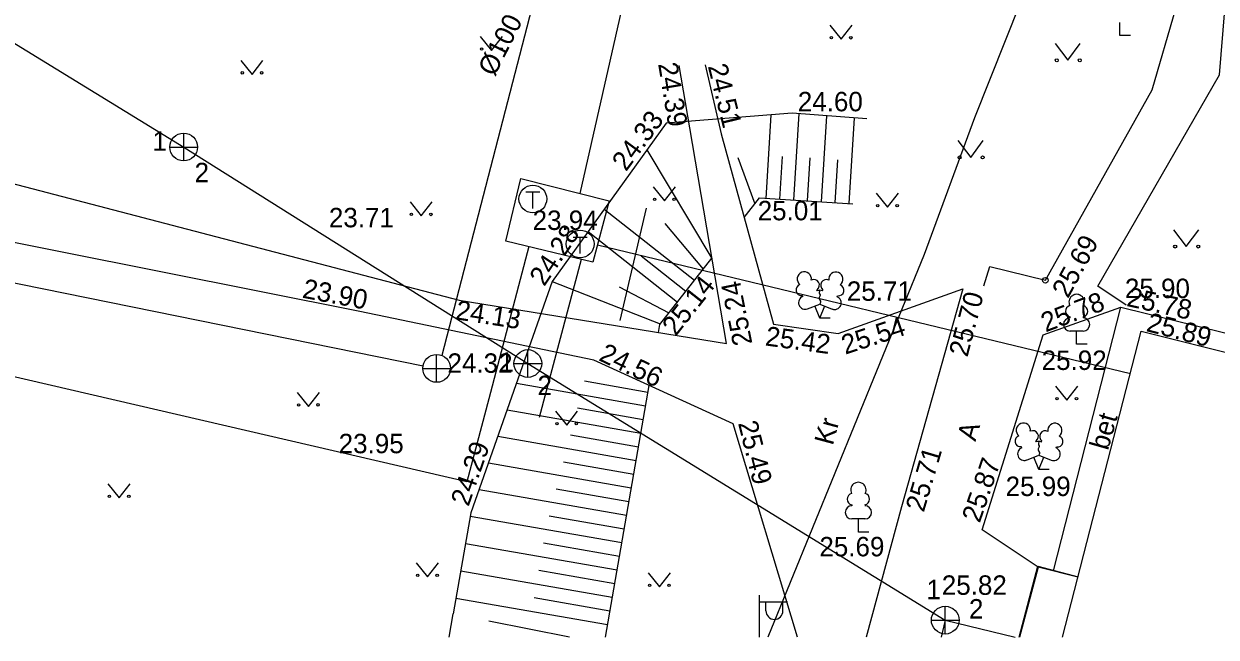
# Model space of a CAD drawing. Extents: x 714391 to 714584, y 6589993 to 6590151.
# Drawn here: x 714490.89 to 714533.84, y 6589992.71 to 6590014.81 of the extents above; entities that cross this region are included whole.
import ezdxf

# ---------------------------------------------------------------- set-up
doc = ezdxf.new("R2010")
doc.units = 0
for name, color, linetype in [('HALJASTUS', 7, 'Continuous'), ('HOONE', 7, 'Continuous'), ('HOONEDET', 7, 'Continuous'), ('KKAEV', 7, 'Continuous'), ('KORGUS', 7, 'Continuous'), ('KTRASS', 7, 'Continuous'), ('MPKAABEL', 7, 'Continuous'), ('POST', 7, 'Continuous'), ('PUU', 7, 'Continuous'), ('RAJATIS', 7, 'Continuous'), ('RELJEEF', 7, 'Continuous'), ('SKTRASS', 7, 'Continuous'), ('TEE', 7, 'Continuous'), ('TKAEV', 7, 'Continuous'), ('TORU NR', 7, 'Continuous'), ('TTRASS', 7, 'Continuous')]:
    doc.layers.add(name, color=color, linetype=linetype)

msp = doc.modelspace()

# ---------------------------------------------------------------- linework, layer by layer
at = {"layer": 'HALJASTUS'}
for p, q in [((714519.929, 6590014.762), (714520.334, 6590014.257)), ((714520.334, 6590014.257), (714520.729, 6590014.762)), ((714507.332, 6590014.356), (714507.737, 6590013.851)), ((714507.737, 6590013.851), (714508.132, 6590014.356)), ((714528.037, 6590014.107), (714528.5, 6590013.5)), ((714528.5, 6590013.5), (714528.946, 6590014.107)), ((714498.707, 6590013.498), (714499.112, 6590012.993)), ((714499.112, 6590012.993), (714499.507, 6590013.498)), ((714524.537, 6590010.607), (714525, 6590010)), ((714525, 6590010), (714525.446, 6590010.607)), ((714513.563, 6590008.937), (714513.968, 6590008.432)), ((714513.968, 6590008.432), (714514.363, 6590008.937)), ((714521.6, 6590008.711), (714522.005, 6590008.206)), ((714522.005, 6590008.206), (714522.4, 6590008.711)), ((714504.803, 6590008.395), (714505.208, 6590007.89)), ((714505.208, 6590007.89), (714505.603, 6590008.395)), ((714532.303, 6590007.395), (714532.766, 6590006.788)), ((714532.766, 6590006.788), (714533.212, 6590007.395)), ((714528.057, 6590001.758), (714528.462, 6590001.253)), ((714528.462, 6590001.253), (714528.857, 6590001.758)), ((714500.739, 6590001.532), (714501.144, 6590001.027)), ((714501.144, 6590001.027), (714501.539, 6590001.532)), ((714510.041, 6590000.855), (714510.446, 6590000.35)), ((714510.446, 6590000.35), (714510.841, 6590000.855)), ((714493.921, 6589998.236), (714494.326, 6589997.731)), ((714494.326, 6589997.731), (714494.721, 6589998.236)), ((714505.029, 6589995.391), (714505.434, 6589994.886)), ((714505.434, 6589994.886), (714505.829, 6589995.391)), ((714513.382, 6589995.03), (714513.787, 6589994.525)), ((714513.787, 6589994.525), (714514.182, 6589995.03))]:
    msp.add_line(p, q, dxfattribs=at)
for centre, radius in [((714519.981, 6590014.312), 0.0428), ((714520.681, 6590014.312), 0.0452), ((714507.384, 6590013.906), 0.0428), ((714508.084, 6590013.906), 0.0452), ((714528.099, 6590013.5), 0.055), ((714528.928, 6590013.5), 0.055), ((714498.759, 6590013.048), 0.0428), ((714499.459, 6590013.048), 0.0452), ((714524.599, 6590010), 0.055), ((714525.428, 6590010), 0.055), ((714513.615, 6590008.488), 0.0428), ((714514.315, 6590008.488), 0.0452), ((714521.652, 6590008.262), 0.0428), ((714522.352, 6590008.262), 0.0452), ((714504.855, 6590007.946), 0.0428), ((714505.555, 6590007.946), 0.0452), ((714532.365, 6590006.788), 0.055), ((714533.194, 6590006.788), 0.055), ((714500.791, 6590001.082), 0.0428), ((714501.491, 6590001.082), 0.0452), ((714528.109, 6590001.308), 0.0428), ((714528.809, 6590001.308), 0.0452), ((714510.093, 6590000.405), 0.0428), ((714510.793, 6590000.405), 0.0452), ((714493.973, 6589997.786), 0.0428), ((714494.673, 6589997.786), 0.0452), ((714505.081, 6589994.942), 0.0428), ((714505.781, 6589994.942), 0.0452), ((714513.434, 6589994.58), 0.0428), ((714514.134, 6589994.58), 0.0452)]:
    msp.add_circle(centre, radius, dxfattribs=at)
at = {"layer": 'HOONE'}
for points in [[(714528.305, 6589992.711), (714531.142, 6590003.734), (714541.598, 6590001.124)], [(714526.74, 6589992.711), (714527.42, 6589995.271), (714528.876, 6589994.89)], [(714527.427, 6589995.234), (714526.753, 6589992.711)]]:
    msp.add_lwpolyline(points, dxfattribs=at)
at = {"layer": 'HOONEDET'}
msp.add_lwpolyline([(714527.976, 6589995.097), (714530.413, 6590004.606), (714540.577, 6590002.096), (714542.446, 6590001.618), (714540.308, 6589992.711)], dxfattribs=at)
at = {"layer": 'KKAEV'}
for p, q in [((714496.65, 6590009.873), (714496.65, 6590010.873)), ((714496.15, 6590010.373), (714497.15, 6590010.373)), ((714505.763, 6590001.896), (714505.763, 6590002.896)), ((714509.047, 6590002.073), (714509.047, 6590003.073)), ((714508.547, 6590002.573), (714509.547, 6590002.573)), ((714505.263, 6590002.396), (714506.263, 6590002.396)), ((714524.082, 6589992.824), (714524.082, 6589993.824)), ((714523.582, 6589993.324), (714524.582, 6589993.324))]:
    msp.add_line(p, q, dxfattribs=at)
for centre in [(714496.65, 6590010.373), (714505.763, 6590002.396), (714509.047, 6590002.573), (714524.082, 6589993.324)]:
    msp.add_circle(centre, 0.5, dxfattribs=at)
at = {"layer": 'KORGUS'}
msp.add_circle((714527.69, 6590005.573), 0.1, dxfattribs=at)
at = {"layer": 'KTRASS'}
for p, q in [((714474.411, 6590024.03), (714496.65, 6590010.373)), ((714496.65, 6590010.373), (714509.047, 6590002.573)), ((714509.047, 6590002.573), (714524.082, 6589993.324)), ((714524.082, 6589993.324), (714523.935, 6589992.711)), ((714524.082, 6589993.324), (714526.599, 6589992.711))]:
    msp.add_line(p, q, dxfattribs=at)
at = {"layer": 'MPKAABEL'}
msp.add_lwpolyline([(714531.176, 6590026.61), (714525.138, 6590011.422), (714523.319, 6590006.504), (714517.694, 6589992.711)], dxfattribs=at)
at = {"layer": 'POST'}
for p, q in [((714517.395, 6589992.711), (714517.395, 6589994.229)), ((714517.395, 6589993.979), (714518.395, 6589993.979)), ((714517.622, 6589993.658), (714517.622, 6589993.979)), ((714518.234, 6589993.658), (714518.234, 6589993.979))]:
    msp.add_line(p, q, dxfattribs=at)
msp.add_arc((714517.928, 6589993.658), 0.306, 180, 0, dxfattribs=at)
at = {"layer": 'PUU'}
for p, q in [((714530.377, 6590014.391), (714530.377, 6590014.866)), ((714530.757, 6590014.391), (714530.377, 6590014.391)), ((714518.947, 6590004.987), (714518.932, 6590005.027)), ((714519.477, 6590005.197), (714519.462, 6590005.232)), ((714519.662, 6590005.192), (714519.677, 6590005.232)), ((714520.187, 6590004.977), (714520.202, 6590005.017)), ((714519.122, 6590004.542), (714519.567, 6590004.717)), ((714519.562, 6590004.207), (714519.387, 6590004.647)), ((714519.562, 6590004.207), (714519.742, 6590004.647)), ((714519.567, 6590004.717), (714520.007, 6590004.537)), ((714519.942, 6590004.207), (714519.562, 6590004.207)), ((714528.576, 6590004.249), (714528.576, 6590004.219)), ((714529.056, 6590004.249), (714529.056, 6590004.219)), ((714529.056, 6590003.744), (714528.576, 6590003.744)), ((714528.816, 6590003.269), (714528.816, 6590003.744)), ((714529.196, 6590003.269), (714528.816, 6590003.269)), ((714526.836, 6589999.539), (714526.821, 6589999.579)), ((714527.366, 6589999.749), (714527.351, 6589999.784)), ((714527.551, 6589999.744), (714527.566, 6589999.784)), ((714528.076, 6589999.529), (714528.091, 6589999.569)), ((714527.011, 6589999.094), (714527.456, 6589999.269)), ((714527.451, 6589998.759), (714527.276, 6589999.199)), ((714527.451, 6589998.759), (714527.631, 6589999.199)), ((714527.456, 6589999.269), (714527.896, 6589999.089)), ((714527.831, 6589998.759), (714527.451, 6589998.759)), ((714520.714, 6589997.476), (714520.714, 6589997.446)), ((714521.194, 6589997.476), (714521.194, 6589997.446)), ((714521.194, 6589996.971), (714520.714, 6589996.971)), ((714520.954, 6589996.496), (714520.954, 6589996.971)), ((714521.334, 6589996.496), (714520.954, 6589996.496))]:
    msp.add_line(p, q, dxfattribs=at)
for points in [[(714519.567, 6590005.212), (714519.547, 6590005.137), (714519.547, 6590005.117), (714519.557, 6590005.087), (714519.577, 6590005.052), (714519.582, 6590005.032), (714519.567, 6590004.997), (714519.542, 6590004.947), (714519.537, 6590004.922), (714519.542, 6590004.907), (714519.552, 6590004.877), (714519.587, 6590004.817), (714519.592, 6590004.797), (714519.587, 6590004.777), (714519.572, 6590004.742), (714519.567, 6590004.717)], [(714527.456, 6589999.764), (714527.436, 6589999.689), (714527.436, 6589999.669), (714527.446, 6589999.639), (714527.466, 6589999.604), (714527.471, 6589999.584), (714527.456, 6589999.549), (714527.431, 6589999.499), (714527.426, 6589999.474), (714527.431, 6589999.459), (714527.441, 6589999.429), (714527.476, 6589999.369), (714527.481, 6589999.349), (714527.476, 6589999.329), (714527.461, 6589999.294), (714527.456, 6589999.269)]]:
    msp.add_lwpolyline(points, dxfattribs=at)
for centre, radius, start, end in [((714519.005, 6590005.621), 0.256, 111.5027, 232.5173), ((714519.005, 6590005.621), 0.256, 350.4856, 111.5002), ((714520.141, 6590005.612), 0.256, 67.6168, 188.6314), ((714520.141, 6590005.612), 0.256, 306.5997, 67.6143), ((714518.906, 6590005.225), 0.202, 106.2979, 277.8684), ((714519.348, 6590005.399), 0.202, 305.1345, 116.705), ((714519.795, 6590005.395), 0.202, 62.412, 233.9825), ((714519.566, 6590004.974), 0.237, 66.7655, 111.5015), ((714520.234, 6590005.215), 0.202, 261.2486, 72.8191), ((714528.816, 6590004.789), 0.277, 332.5799, 207.4201), ((714528.816, 6590004.789), 0.277, 58.4864, 121.5136), ((714519.036, 6590004.765), 0.237, 111.5014, 291.5004), ((714520.097, 6590004.757), 0.237, 247.6166, 67.6155), ((714528.626, 6590004.457), 0.212, 105.2441, 257.079), ((714529.006, 6590004.457), 0.212, 282.921, 74.7559), ((714528.578, 6590003.981), 0.237, 90, 270), ((714529.053, 6590003.981), 0.237, 270, 90), ((714526.894, 6590000.173), 0.256, 111.5027, 232.5173), ((714526.894, 6590000.173), 0.256, 350.4856, 111.5002), ((714528.03, 6590000.164), 0.256, 67.6168, 188.6314), ((714528.03, 6590000.164), 0.256, 306.5997, 67.6143), ((714526.795, 6589999.777), 0.202, 106.2979, 277.8684), ((714527.237, 6589999.951), 0.202, 305.1345, 116.705), ((714527.684, 6589999.947), 0.202, 62.412, 233.9825), ((714528.123, 6589999.767), 0.202, 261.2486, 72.8191), ((714526.925, 6589999.317), 0.237, 111.5014, 291.5004), ((714527.455, 6589999.526), 0.237, 66.7655, 111.5015), ((714527.986, 6589999.309), 0.237, 247.6166, 67.6155), ((714520.954, 6589998.016), 0.277, 332.5799, 207.4201), ((714520.764, 6589997.684), 0.212, 105.2441, 257.079), ((714521.144, 6589997.684), 0.212, 282.921, 74.7559), ((714520.716, 6589997.209), 0.237, 90, 270), ((714521.191, 6589997.209), 0.237, 270, 90)]:
    msp.add_arc(centre, radius, start, end, dxfattribs=at)
at = {"layer": 'RAJATIS'}
msp.add_line((714513.314, 6590008.168), (714512.359, 6590004.124), dxfattribs=at)
at = {"layer": 'RELJEEF'}
for p, q in [((714517.802, 6590011.536), (714517.614, 6590008.525)), ((714518.807, 6590011.578), (714518.612, 6590008.463)), ((714519.804, 6590011.504), (714519.61, 6590008.4)), ((714520.802, 6590011.429), (714520.608, 6590008.338)), ((714513.336, 6590010.274), (714515.672, 6590006.359)), ((714516.609, 6590009.998), (714517.22, 6590008.322)), ((714518.21, 6590010.035), (714518.113, 6590008.494)), ((714519.209, 6590009.986), (714519.111, 6590008.431)), ((714520.206, 6590009.918), (714520.109, 6590008.369)), ((714511.8, 6590008.139), (714515.052, 6590005.574)), ((714513.976, 6590007.615), (714515.362, 6590005.967)), ((714511.215, 6590007.327), (714514.433, 6590004.789)), ((714513.125, 6590006.457), (714514.743, 6590005.182)), ((714509.921, 6590005.528), (714513.814, 6590004.004)), ((714512.335, 6590005.341), (714514.123, 6590004.396)), ((714508.633, 6590001.862), (714513.289, 6590001.053)), ((714511.088, 6590001.943), (714513.374, 6590001.546)), ((714508.297, 6590000.906), (714513.117, 6590000.068)), ((714510.834, 6590000.972), (714513.203, 6590000.561)), ((714507.961, 6589999.949), (714512.946, 6589999.083)), ((714510.58, 6590000.001), (714513.032, 6589999.575)), ((714507.625, 6589998.993), (714512.775, 6589998.098)), ((714510.327, 6589999.03), (714512.861, 6589998.59)), ((714507.289, 6589998.036), (714512.604, 6589997.112)), ((714510.073, 6589998.06), (714512.689, 6589997.605)), ((714506.972, 6589997.076), (714512.433, 6589996.127)), ((714509.819, 6589997.089), (714512.518, 6589996.62)), ((714506.8, 6589996.091), (714512.261, 6589995.142)), ((714509.617, 6589996.109), (714512.347, 6589995.634)), ((714509.445, 6589995.124), (714512.176, 6589994.649)), ((714506.628, 6589995.106), (714512.09, 6589994.157)), ((714506.457, 6589994.121), (714511.919, 6589993.171)), ((714509.273, 6589994.139), (714512.004, 6589993.664)), ((714510.553, 6589992.711), (714507.637, 6589993.287))]:
    msp.add_line(p, q, dxfattribs=at)
for points in [[(714521.262, 6590011.395), (714518.567, 6590011.596), (714514.029, 6590011.237), (714509.921, 6590005.528), (714506.993, 6589997.195), (714506.358, 6589993.553)], [(714516.84, 6590007.84), (714517.391, 6590008.539), (714520.751, 6590008.329)], [(714513.748, 6590003.694), (714513.798, 6590003.984), (714515.68, 6590006.37)], [(714511.839, 6589992.712), (714513.416, 6590001.784)], [(714506.211, 6589992.711), (714506.358, 6589993.553)]]:
    msp.add_lwpolyline(points, dxfattribs=at)
at = {"layer": 'SKTRASS'}
msp.add_line((714477.747, 6590008.073), (714505.271, 6590002.487), dxfattribs=at)
msp.add_lwpolyline([(714531.495, 6590096.001), (714522.972, 6590065.168), (714519.718, 6590053.426), (714509.807, 6590017.772), (714505.951, 6590002.864)], dxfattribs=at)
at = {"layer": 'TEE'}
for points in [[(714525.477, 6590005.373), (714525.684, 6590006.074), (714527.69, 6590005.573), (714531.538, 6590012.432), (714532.385, 6590015.369), (714531.445, 6590019.084), (714529.795, 6590023.709), (714527.067, 6590029.841), (714526.32, 6590032.242), (714526.158, 6590034.948), (714527.384, 6590039.748), (714530.089, 6590049.424), (714531.112, 6590053.289), (714520.888, 6590055.232), (714516.962, 6590040.074), (714512.15, 6590039.854), (714507.831, 6590037.94), (714505.233, 6590035.896), (714491.681, 6590027.029), (714484.169, 6590021.661), (714470.258, 6590012.413)], [(714530.594, 6590004.671), (714529.575, 6590005.355), (714533.957, 6590012.977), (714534.157, 6590015.322), (714534.216, 6590016.497), (714533.749, 6590019.201), (714531.843, 6590023.902), (714529.246, 6590029.211), (714527.989, 6590032.696), (714528.19, 6590034.745), (714530.462, 6590043.175), (714532.838, 6590052.177), (714538.719, 6590050.416), (714545.918, 6590048.286), (714551.944, 6590046.002), (714557.184, 6590043.351), (714560.131, 6590041.46), (714562.296, 6590039.644), (714565.486, 6590037.034), (714564.832, 6590036.22), (714560.292, 6590037.889), (714555.09, 6590040.381)], [(714470.258, 6590012.413), (714477.939, 6590012.342), (714506.57, 6590004.861), (714516.206, 6590003.294), (714514.878, 6590011.068), (714514.502, 6590013.311)], [(714515.436, 6590013.332), (714516.012, 6590010.855), (714517.897, 6590003.992), (714520.223, 6590003.651), (714524.712, 6590005.259)], [(714518.759, 6589992.711), (714516.445, 6590000.399), (714511.421, 6590002.696), (714502.998, 6590004.442), (714477.749, 6590009.482), (714469.779, 6590010.286), (714458.4, 6590011.077)], [(714524.712, 6590005.259), (714522.502, 6589997.408), (714521.23, 6589992.711)], [(714528.862, 6589994.877), (714527.427, 6589995.234), (714525.418, 6589996.584), (714527.608, 6590003.602), (714530.413, 6590004.606)]]:
    msp.add_lwpolyline(points, dxfattribs=at)
at = {"layer": 'TKAEV'}
for p, q in [((714508.978, 6590008.754), (714509.478, 6590008.754)), ((714509.228, 6590008.154), (714509.228, 6590008.754)), ((714510.682, 6590007.132), (714511.182, 6590007.132)), ((714510.932, 6590006.532), (714510.932, 6590007.132))]:
    msp.add_line(p, q, dxfattribs=at)
for centre in [(714509.228, 6590008.504), (714510.932, 6590006.882)]:
    msp.add_circle(centre, 0.5, dxfattribs=at)
at = {"layer": 'TTRASS'}
msp.add_line((714511.554, 6590006.854), (714530.751, 6590002.215), dxfattribs=at)
for points in [[(714510.928, 6590008.703), (714512.829, 6590017.079), (714522.511, 6590055.684), (714522.522, 6590055.681), (714534.537, 6590104.393)], [(714509.087, 6590006.785), (714507.645, 6590001.299), (714506.85, 6589998.309), (714488.558, 6590002.554)], [(714510.967, 6590006.327), (714509.455, 6590000.622)]]:
    msp.add_lwpolyline(points, dxfattribs=at)
msp.add_lwpolyline([(714508.793, 6590009.245), (714511.971, 6590008.438), (714511.388, 6590006.225), (714508.259, 6590006.986)], close=True, dxfattribs=at)

# ---------------------------------------------------------------- texts
at = {"layer": 'HOONEDET'}
msp.add_text('bet', height=0.7, rotation=74.1412, dxfattribs=at).set_placement((714529.944, 6589999.414))
at = {"layer": 'KORGUS'}
for s, rotation, p in [('24.39', 279.315, (714513.738, 6590013.371)), ('24.51', 283.8942, (714515.527, 6590013.287)), ('24.33', 53.5231, (714512.584, 6590009.466)), ('24.28', 56.2393, (714509.638, 6590005.323)), ('25.69', 61.277, (714528.504, 6590004.893)), ('23.90', 349.3641, (714500.896, 6590004.948)), ('25.14', 51.789, (714514.379, 6590003.535)), ('25.24', 101.2225, (714517.139, 6590003.293)), ('25.70', 75.3148, (714524.881, 6590002.779)), ('25.78', 20.7651, (714527.696, 6590003.691)), ('25.78', 347.5926, (714530.586, 6590004.651)), ('24.13', 351.2026, (714506.415, 6590004.169)), ('25.54', 18.1219, (714520.48, 6590002.889)), ('25.89', 345.5216, (714531.292, 6590003.746)), ('25.42', 352.316, (714517.573, 6590003.226)), ('24.56', 334.5279, (714511.568, 6590002.702)), ('25.49', 284.0362, (714516.616, 6590000.424)), ('24.29', 70.7225, (714506.91, 6589997.394)), ('25.71', 73.5155, (714523.308, 6589997.187)), ('25.87', 71.0822, (714525.324, 6589996.801))]:
    msp.add_text(s, height=0.7, rotation=rotation, dxfattribs=at).set_placement(p)
for s, p in [('24.60', (714518.771, 6590011.662)), ('25.01', (714517.327, 6590007.734)), ('23.71', (714501.881, 6590007.482)), ('23.94', (714509.22, 6590007.386)), ('25.71', (714520.537, 6590004.832)), ('25.90', (714530.554, 6590004.931)), ('24.32', (714506.154, 6590002.238)), ('25.92', (714527.556, 6590002.341)), ('23.95', (714502.233, 6589999.339)), ('25.99', (714526.258, 6589997.797)), ('25.69', (714519.549, 6589995.624)), ('25.82', (714523.958, 6589994.237))]:
    msp.add_text(s, height=0.7, dxfattribs=at).set_placement(p)
at = {"layer": 'SKTRASS'}
msp.add_text('%%c100', height=0.7, rotation=63.1575, dxfattribs=at).set_placement((714507.843, 6590012.885))
at = {"layer": 'TEE'}
for s, rotation, p in [('Kr', 74.9869, (714520.031, 6589999.595)), ('A', 73.9229, (714525.171, 6589999.743))]:
    msp.add_text(s, height=0.7, rotation=rotation, dxfattribs=at).set_placement(p)
at = {"layer": 'TORU NR'}
for s, p in [('1', (714495.522, 6590010.24)), ('2', (714497.044, 6590009.106)), ('1', (714508.02, 6590002.279)), ('2', (714509.394, 6590001.433)), ('1', (714523.405, 6589994.079)), ('2', (714524.937, 6589993.383))]:
    msp.add_text(s, height=0.7, dxfattribs=at).set_placement(p)

doc.saveas('drawing.dxf')
